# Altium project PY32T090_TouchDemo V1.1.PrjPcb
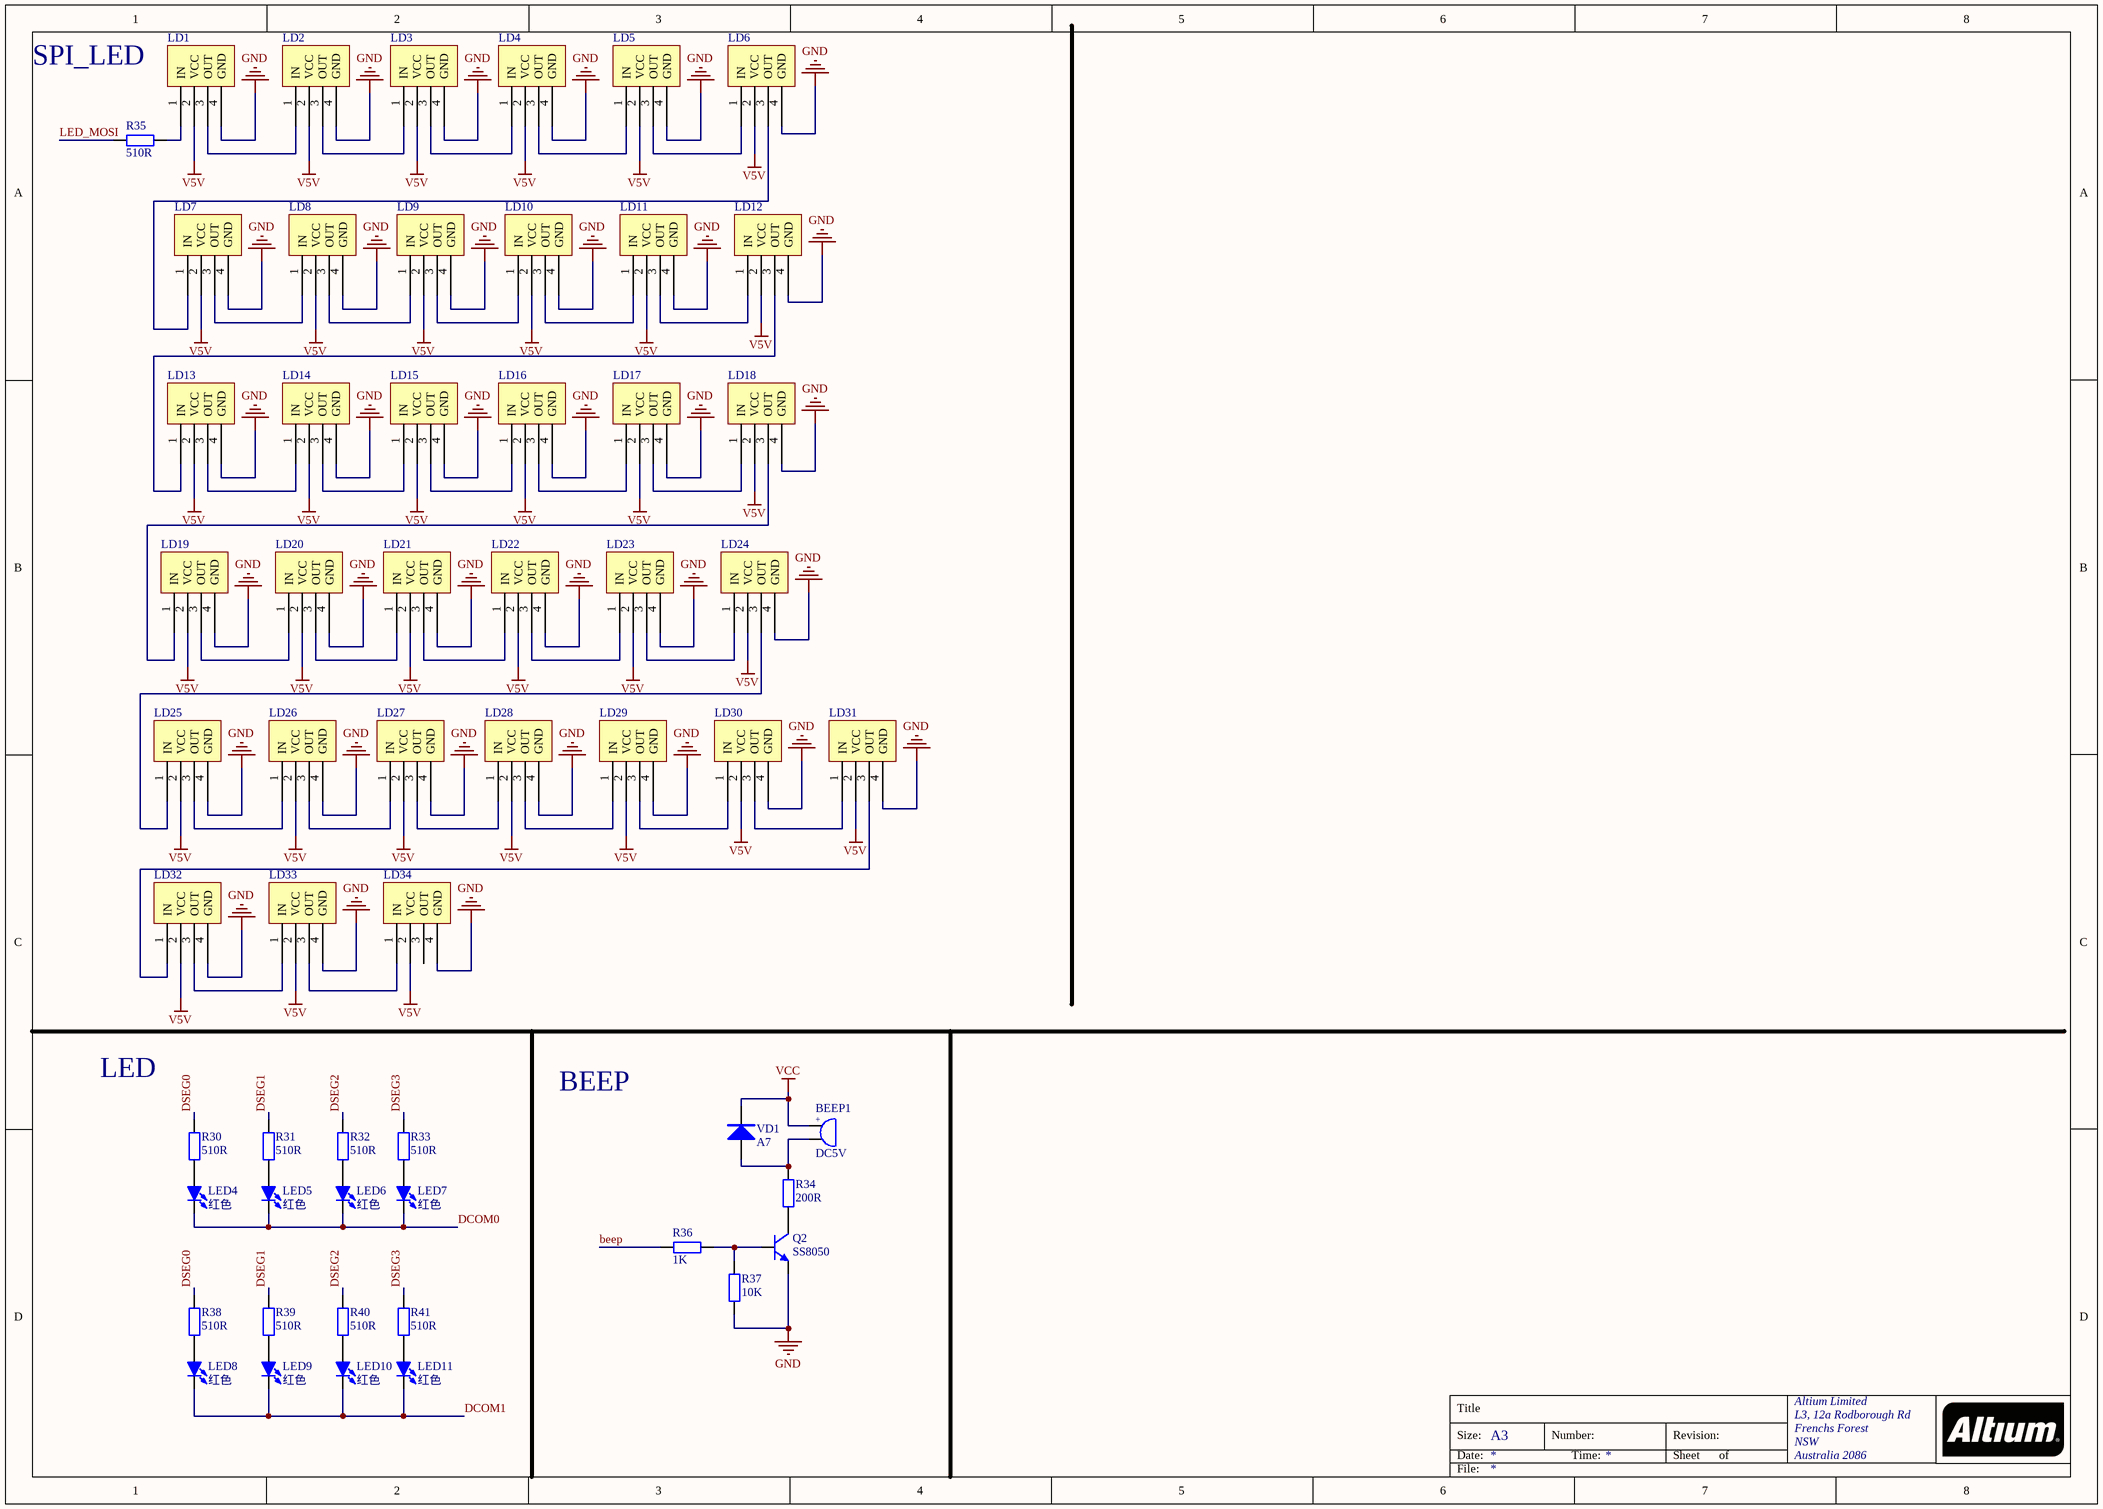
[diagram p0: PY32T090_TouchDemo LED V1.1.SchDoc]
2 sheets, 150 parts. Net scope: global (net labels, ports and power ports of the same name join across sheets).
Board file: PY32T090_TouchDemo V1.1.PcbDoc
Sheets:
  PY32T090_TouchDemo LED V1.1.SchDoc
  PY32T090_TouchDemo V1.1.SchDoc

## Sheet PY32T090_TouchDemo LED V1.1.SchDoc
size A3; Organization: Altium Limited; Address1: L3, 12a Rodborough Rd; Address2: Frenchs Forest; Address3: NSW; Address4: Australia 2086

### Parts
BEEP1  DC5V  [BEEP 5x9x5.5]
LD1  LED1  [LED_WS]  (value not drawn)
LD2  LED1  [LED_WS]  (value not drawn)
LD3  LED1  [LED_WS]  (value not drawn)
LD4  LED1  [LED_WS]  (value not drawn)
LD5  LED1  [LED_WS]  (value not drawn)
LD6  LED1  [LED_WS]  (value not drawn)
LD7  LED1  [LED_WS]  (value not drawn)
LD8  LED1  [LED_WS]  (value not drawn)
LD9  LED1  [LED_WS]  (value not drawn)
LD10  LED1  [LED_WS]  (value not drawn)
LD11  LED1  [LED_WS]  (value not drawn)
LD12  LED1  [LED_WS]  (value not drawn)
LD13  LED1  [LED_WS]  (value not drawn)
LD14  LED1  [LED_WS]  (value not drawn)
LD15  LED1  [LED_WS]  (value not drawn)
LD16  LED1  [LED_WS]  (value not drawn)
LD17  LED1  [LED_WS]  (value not drawn)
LD18  LED1  [LED_WS]  (value not drawn)
LD19  LED1  [LED_WS]  (value not drawn)
LD20  LED1  [LED_WS]  (value not drawn)
LD21  LED1  [LED_WS]  (value not drawn)
LD22  LED1  [LED_WS]  (value not drawn)
LD23  LED1  [LED_WS]  (value not drawn)
LD24  LED1  [LED_WS]  (value not drawn)
LD25  LED1  [LED_WS]  (value not drawn)
LD26  LED1  [LED_WS]  (value not drawn)
LD27  LED1  [LED_WS]  (value not drawn)
LD28  LED1  [LED_WS]  (value not drawn)
LD29  LED1  [LED_WS]  (value not drawn)
LD30  LED1  [LED_WS]  (value not drawn)
LD31  LED1  [LED_WS]  (value not drawn)
LD32  LED1  [LED_WS]  (value not drawn)
LD33  LED1  [LED_WS]  (value not drawn)
LD34  LED1  [LED_WS]  (value not drawn)
LED4  红色  [LED 0805G]
LED5  红色  [LED 0805G]
LED6  红色  [LED 0805G]
LED7  红色  [LED 0805G]
LED8  红色  [LED 0805G]
LED9  红色  [LED 0805G]
LED10  红色  [LED 0805G]
LED11  红色  [LED 0805G]
Q2  SS8050  [SOT23-3L]
R30  510R  [R 0603_L]
R31  510R  [R 0603_L]
R32  510R  [R 0603_L]
R33  510R  [R 0603_L]
R34  200R  [R 0603_L]
R35  510R  [R 0603_L]
R36  1K  [R 0603_L]
R37  10K  [R 0603_L]
R38  510R  [R 0603_L]
R39  510R  [R 0603_L]
R40  510R  [R 0603_L]
R41  510R  [R 0603_L]
VD1  A7  [SOD-123]

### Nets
GND: LD1.4(GND) LD2.4(GND) LD3.4(GND) LD4.4(GND) LD5.4(GND) LD6.4(GND) LD7.4(GND) LD8.4(GND) LD9.4(GND) LD10.4(GND) LD11.4(GND) LD12.4(GND) LD13.4(GND) LD14.4(GND) LD15.4(GND) LD16.4(GND) LD17.4(GND) LD18.4(GND) LD19.4(GND) LD20.4(GND) LD21.4(GND) LD22.4(GND) LD23.4(GND) LD24.4(GND) LD25.4(GND) LD26.4(GND) LD27.4(GND) LD28.4(GND) LD29.4(GND) LD30.4(GND) LD31.4(GND) LD32.4(GND) LD33.4(GND) LD34.4(GND) Q2.2(B) R37.1
V5V: LD1.2(VCC) LD2.2(VCC) LD3.2(VCC) LD4.2(VCC) LD5.2(VCC) LD6.2(VCC) LD7.2(VCC) LD8.2(VCC) LD9.2(VCC) LD10.2(VCC) LD11.2(VCC) LD12.2(VCC) LD13.2(VCC) LD14.2(VCC) LD15.2(VCC) LD16.2(VCC) LD17.2(VCC) LD18.2(VCC) LD19.2(VCC) LD20.2(VCC) LD21.2(VCC) LD22.2(VCC) LD23.2(VCC) LD24.2(VCC) LD25.2(VCC) LD26.2(VCC) LD27.2(VCC) LD28.2(VCC) LD29.2(VCC) LD30.2(VCC) LD31.2(VCC) LD32.2(VCC) LD33.2(VCC) LD34.2(VCC)
VCC: BEEP1.1 VD1.K
beep: R36.2
DCOM0: LED4.2(K) LED5.2(K) LED6.2(K) LED7.2(K)
DCOM1: LED8.2(K) LED9.2(K) LED10.2(K) LED11.2(K)
DSEG0: R30.1 R38.1
DSEG1: R31.1 R39.1
DSEG2: R32.1 R40.1
DSEG3: R33.1 R41.1
LED_MOSI: R35.1
NetBEEP1_2: BEEP1.2 R34.2 VD1.A
NetLD1_1: LD1.1(IN) R35.2
NetLD1_3: LD1.3(OUT) LD2.1(IN)
NetLD2_3: LD2.3(OUT) LD3.1(IN)
NetLD3_3: LD3.3(OUT) LD4.1(IN)
NetLD4_3: LD4.3(OUT) LD5.1(IN)
NetLD5_3: LD5.3(OUT) LD6.1(IN)
NetLD6_3: LD6.3(OUT) LD7.1(IN)
NetLD7_3: LD7.3(OUT) LD8.1(IN)
NetLD8_3: LD8.3(OUT) LD9.1(IN)
NetLD9_3: LD9.3(OUT) LD10.1(IN)
NetLD10_3: LD10.3(OUT) LD11.1(IN)
NetLD11_3: LD11.3(OUT) LD12.1(IN)
NetLD12_3: LD12.3(OUT) LD13.1(IN)
NetLD13_3: LD13.3(OUT) LD14.1(IN)
NetLD14_3: LD14.3(OUT) LD15.1(IN)
NetLD15_3: LD15.3(OUT) LD16.1(IN)
NetLD16_3: LD16.3(OUT) LD17.1(IN)
NetLD17_3: LD17.3(OUT) LD18.1(IN)
NetLD18_3: LD18.3(OUT) LD19.1(IN)
NetLD19_3: LD19.3(OUT) LD20.1(IN)
NetLD20_3: LD20.3(OUT) LD21.1(IN)
NetLD21_3: LD21.3(OUT) LD22.1(IN)
NetLD22_3: LD22.3(OUT) LD23.1(IN)
NetLD23_3: LD23.3(OUT) LD24.1(IN)
NetLD24_3: LD24.3(OUT) LD25.1(IN)
NetLD25_3: LD25.3(OUT) LD26.1(IN)
NetLD26_3: LD26.3(OUT) LD27.1(IN)
NetLD27_3: LD27.3(OUT) LD28.1(IN)
NetLD28_3: LD28.3(OUT) LD29.1(IN)
NetLD29_3: LD29.3(OUT) LD30.1(IN)
NetLD30_3: LD30.3(OUT) LD31.1(IN)
NetLD31_3: LD31.3(OUT) LD32.1(IN)
NetLD32_3: LD32.3(OUT) LD33.1(IN)
NetLD33_3: LD33.3(OUT) LD34.1(IN)
NetLED4_1: LED4.1(A) R30.2
NetLED5_1: LED5.1(A) R31.2
NetLED6_1: LED6.1(A) R32.2
NetLED7_1: LED7.1(A) R33.2
NetLED8_1: LED8.1(A) R38.2
NetLED9_1: LED9.1(A) R39.2
NetLED10_1: LED10.1(A) R40.2
NetLED11_1: LED11.1(A) R41.2
NetQ2_1: Q2.1(E) R36.1 R37.2
NetQ2_3: Q2.3(C) R34.1

Not connected (* = marked no-connect by the designer): LD34 3(OUT)

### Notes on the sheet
- SPI_LED
- LED
- BEEP

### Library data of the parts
BEEP1 = BEEP: 蜂鸣器; 版权归属: 源创客
LD1-LD34 = LED4020
LED4-LED11 = LED-SMD: 贴片LED; 版权归属: 源创客
Q2 = 8050-DIP: 高频放大-NPN型; 版权归属: 源创客; 属性: 40V 1.5A 1W 100MHZ
R30-R41 = R: 贴片电阻; 版权归属: 源创客
VD1 = DIODE

## Sheet PY32T090_TouchDemo V1.1.SchDoc
size A3; SheetNumber: 1; SheetTotal: 1
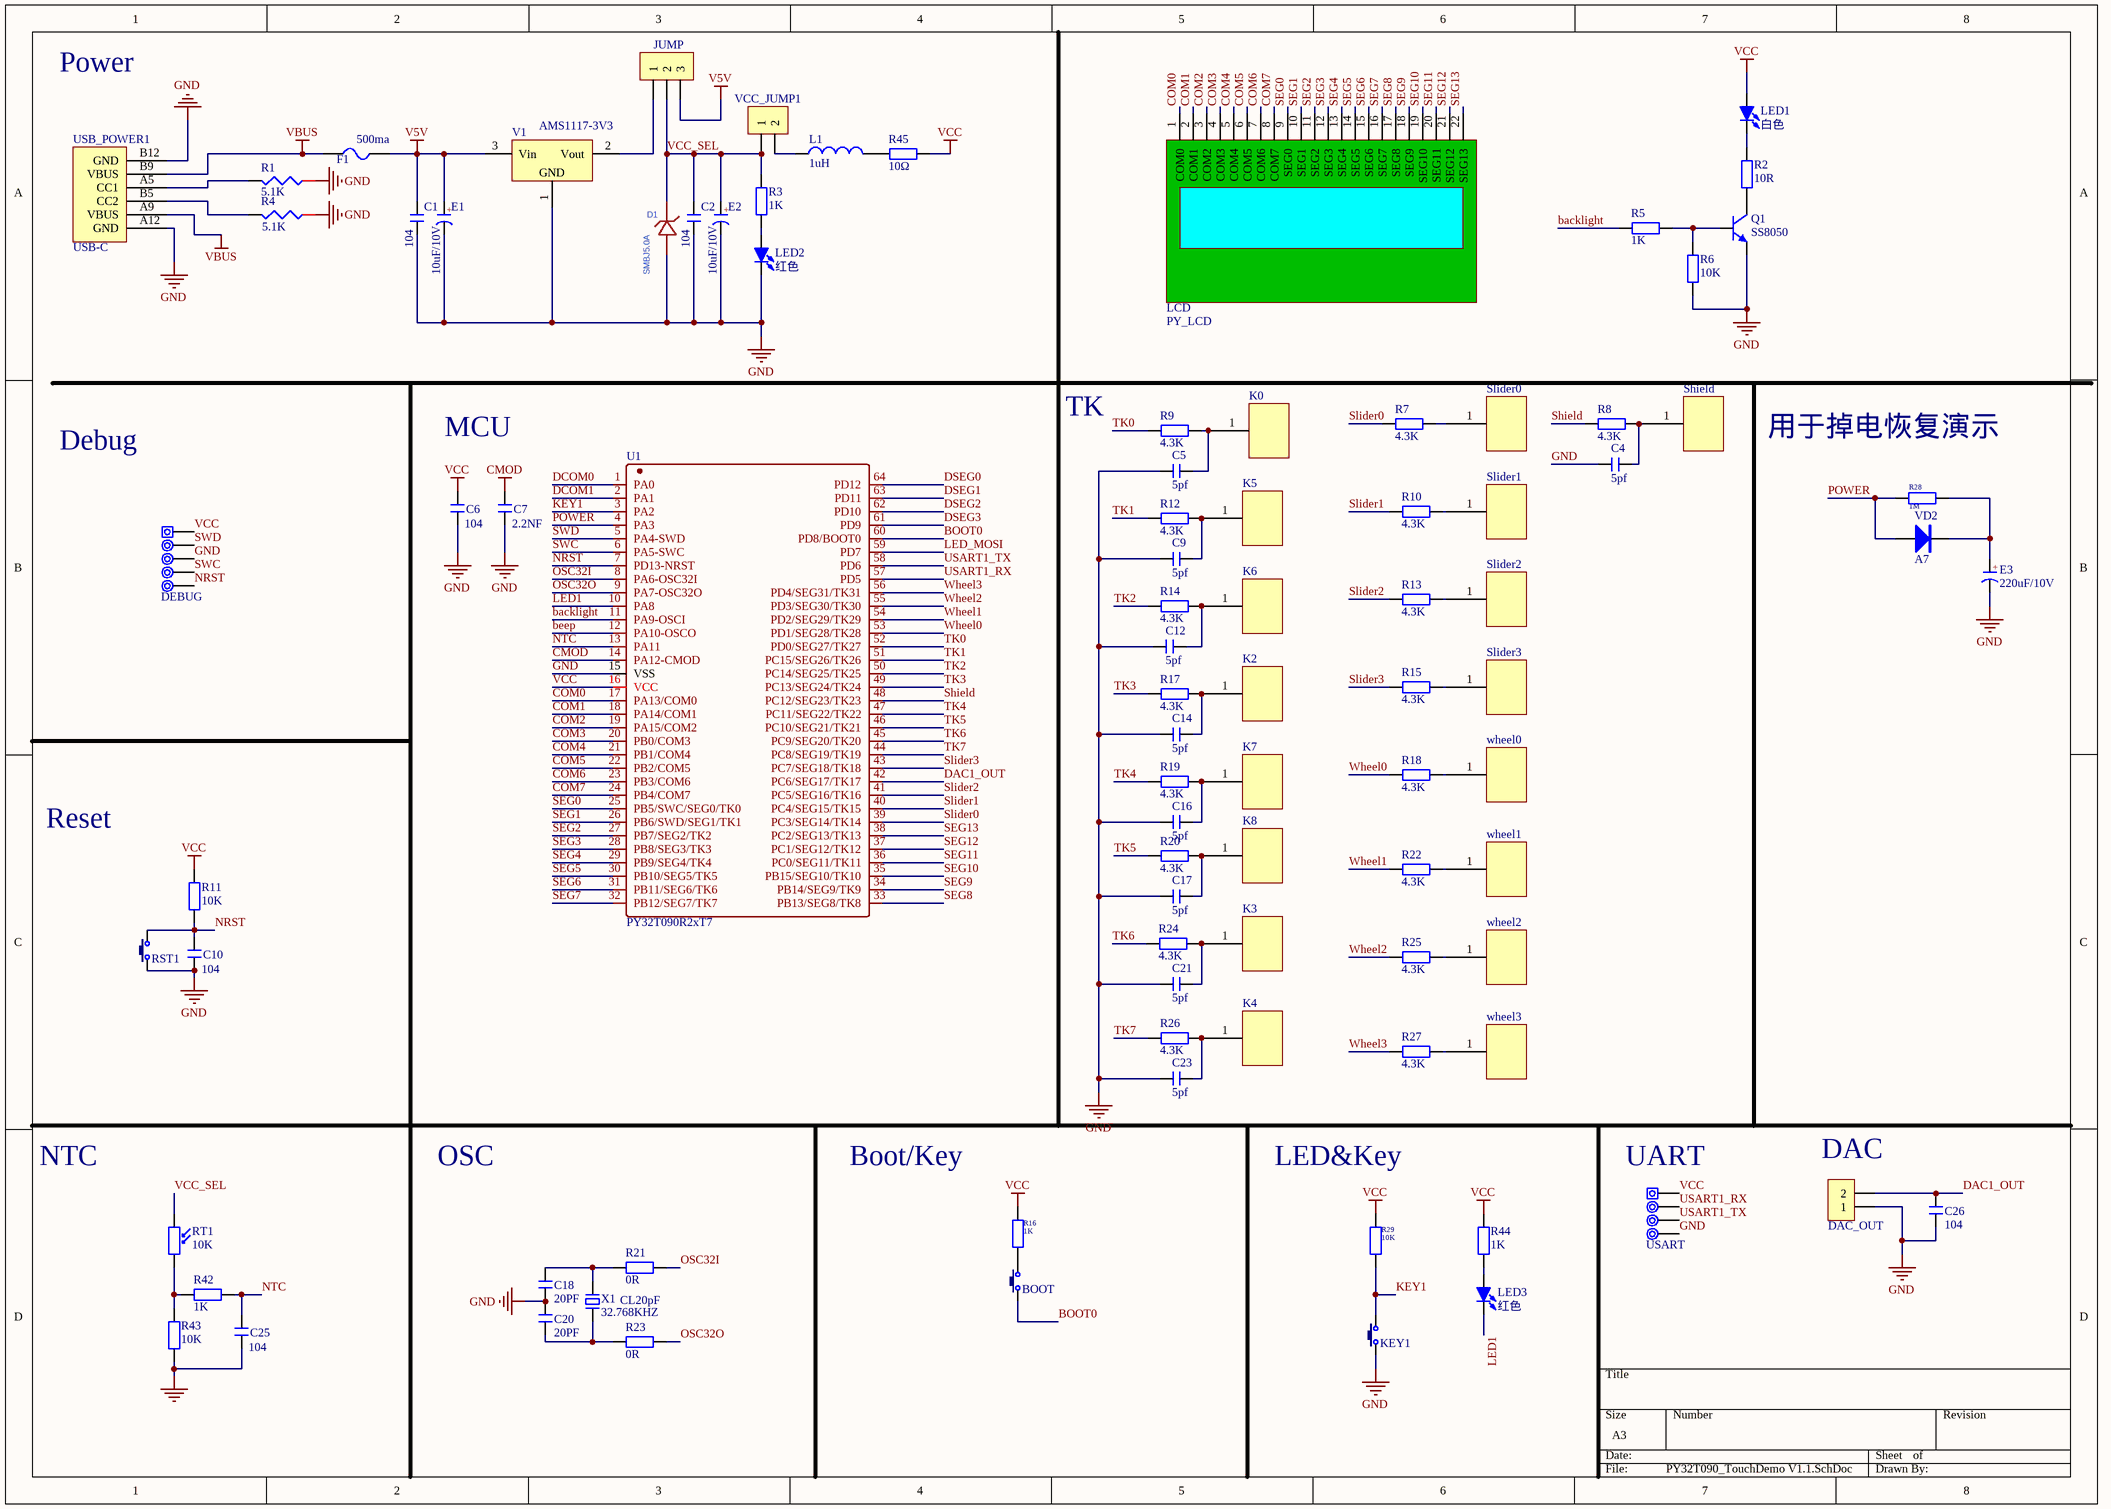
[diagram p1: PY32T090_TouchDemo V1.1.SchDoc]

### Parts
BOOT  6x6x5  [TSW SMD-3*6*5]  (value not drawn)
C1  104  [C 0603_L]
C2  104  [C 0603_L]
C4  5pf  [C 0603_L]
C5  5pf  [C 0603_L]
C6  104  [C 0603_L]
C7  2.2NF  [C 0603_L]
C9  5pf  [C 0603_L]
C10  104  [C 0603_L]
C12  5pf  [C 0603_L]
C14  5pf  [C 0603_L]
C16  5pf  [C 0603_L]
C17  5pf  [C 0603_L]
C18  20PF  [C 0603_L]
C20  20PF  [C 0603_L]
C21  5pf  [C 0603_L]
C23  5pf  [C 0603_L]
C25  104  [C 0603_L]
C26  104  [C 0603_L]
D1  SMBJ5.0A  [SMB_L4.6-W3.6-LS5.3-RD]
DAC_OUT  HDR-1X2  [HDR2.54-LI-2P]  (value not drawn)
DEBUG  ISP  [ISP_DIP_2.54_5P]  (value not drawn)
E1  10uF/10V  [C 0805_L]
E2  10uF/10V  [C 0805_L]
E3  220uF/10V  [CM A(3*5.4)]
F1  500ma  [FU 0805]
JUMP  HDR-1X3  [HDR2.54-LI-3P]  (value not drawn)
K0  Comment  [T-LED]  (value not drawn)
K2  Comment  [T-LED]  (value not drawn)
K3  Comment  [T-LED]  (value not drawn)
K4  Comment  [T-LED]  (value not drawn)
K5  Comment  [T-LED]  (value not drawn)
K6  Comment  [T-LED]  (value not drawn)
K7  Comment  [T-LED]  (value not drawn)
K8  Comment  [T-LED]  (value not drawn)
KEY1  6x6x5  [TSW SMD-3*6*5]  (value not drawn)
L1  1uH  [L 0805_L]
LCD  PY_LCD  [HDR2.54-WI-2x11P]
LED1  白色  [LED 0805G]
LED2  红色  [LED 0805W]
LED3  红色  [LED 0805W]
Q1  SS8050  [SOT23-3L]
R1  5.1K  [R 0603_L]
R2  10R  [R 0805_L]
R3  1K  [R 0603_L]
R4  5.1K  [R 0603_L]
R5  1K  [R 0603_L]
R6  10K  [R 0603_L]
R7  4.3K  [R 0603_L]
R8  4.3K  [R 0603_L]
R9  4.3K  [R 0603_L]
R10  4.3K  [R 0603_L]
R11  10K  [R 0603_L]
R12  4.3K  [R 0603_L]
R13  4.3K  [R 0603_L]
R14  4.3K  [R 0603_L]
R15  4.3K  [R 0603_L]
R16  1K  [R 0603_L]
R17  4.3K  [R 0603_L]
R18  4.3K  [R 0603_L]
R19  4.3K  [R 0603_L]
R20  4.3K  [R 0603_L]
R21  0R  [R 0603_L]
R22  4.3K  [R 0603_L]
R23  0R  [R 0603_L]
R24  4.3K  [R 0603_L]
R25  4.3K  [R 0603_L]
R26  4.3K  [R 0603_L]
R27  4.3K  [R 0603_L]
R28  1M  [R 0603_L]
R29  10K  [R 0603_L]
R42  1K  [R 0603_L]
R43  10K  [R 0603_L]
R44  1K  [R 0603_L]
R45  10Ω  [R 0805_L]
RST1  6x6x5  [TSW SMD-3*6*5]  (value not drawn)
RT1  10K  [RG5528]
Shield  Comment  [T-LED]  (value not drawn)
Slider0  Comment  [T-LED]  (value not drawn)
Slider1  Comment  [T-LED]  (value not drawn)
Slider2  Comment  [T-LED]  (value not drawn)
Slider3  Comment  [T-LED]  (value not drawn)
U1  PY32T090R2xT7  [LQFP64 10x10_L]
USART  ISP  [ISP_DIP_2.54_4P]  (value not drawn)
USB_POWER1  USB-C  [USB-C/S_C]
V1  AMS1117-3V3  [SOT223_N]
VCC_JUMP1  HDR-1X2  [HDR2.54-LI-2P]  (value not drawn)
VD2  A7  [SOD-123]
wheel0  Comment  [T-LED]  (value not drawn)
wheel1  Comment  [T-LED]  (value not drawn)
wheel2  Comment  [T-LED]  (value not drawn)
wheel3  Comment  [T-LED]  (value not drawn)
X1  32.768KHZ  负载电容: CL20pF  [OSC-3x8-WI-A]

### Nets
CMOD: C7.2 U1.14(PA12-CMOD)
GND: C1.1 C2.1 C4.1 C5.1 C6.1 C7.1 C9.1 C10.1 C12.1 C14.1 C16.1 C17.1 C18.1 C20.2 C21.1 C23.1 C25.1 C26.1 D1.2 DAC_OUT.1 DEBUG.3 E1.2(K) E2.2(K) E3.2(K) KEY1.1 LED2.2(K) Q1.2(B) R1.1 R4.1 R6.1 R43.2 RST1.1 U1.15(VSS) USART.4 USB_POWER1.A12(GND) USB_POWER1.B12(GND) V1.1(GND)
V5V: C1.2 E1.1(A) F1.2 JUMP.3 V1.3(Vin)
VBUS: F1.1 USB_POWER1.A9(VBUS) USB_POWER1.B9(VBUS)
VCC: C6.2 DEBUG.1 LED1.1(A) R11.2 R16.2 R29.2 R44.2 R45.2 U1.16(VCC) USART.1
backlight: R5.2 U1.11(PA9-OSCI)
beep: U1.12(PA10-OSCO)
BOOT0: BOOT.1 U1.60(PD8/BOOT0)
COM0: LCD.1(COM0) U1.17(PA13/COM0)
COM1: LCD.2(COM1) U1.18(PA14/COM1)
COM2: LCD.3(COM2) U1.19(PA15/COM2)
COM3: LCD.4(COM3) U1.20(PB0/COM3)
COM4: LCD.5(COM4) U1.21(PB1/COM4)
COM5: LCD.6(COM5) U1.22(PB2/COM5)
COM6: LCD.7(COM6) U1.23(PB3/COM6)
COM7: LCD.8(COM7) U1.24(PB4/COM7)
DAC1_OUT: C26.2 DAC_OUT.2 U1.42(PC6/SEG17/TK17)
DCOM0: U1.1(PA0)
DCOM1: U1.2(PA1)
DSEG0: U1.64(PD12)
DSEG1: U1.63(PD11)
DSEG2: U1.62(PD10)
DSEG3: U1.61(PD9)
KEY1: KEY1.2 R29.1 U1.3(PA2)
LED1: LED3.2(K) U1.10(PA8)
LED_MOSI: U1.59(PD7)
NRST: C10.2 DEBUG.5 R11.1 RST1.2 U1.7(PD13-NRST)
NTC: C25.2 R42.2 U1.13(PA11)
OSC32I: R21.1 U1.8(PA6-OSC32I)
OSC32O: R23.1 U1.9(PA7-OSC32O)
POWER: R28.1 U1.4(PA3) VD2.A
SEG0: LCD.9(SEG0) U1.25(PB5/SWC/SEG0/TK0)
SEG1: LCD.10(SEG1) U1.26(PB6/SWD/SEG1/TK1)
SEG2: LCD.11(SEG2) U1.27(PB7/SEG2/TK2)
SEG3: LCD.12(SEG3) U1.28(PB8/SEG3/TK3)
SEG4: LCD.13(SEG4) U1.29(PB9/SEG4/TK4)
SEG5: LCD.14(SEG5) U1.30(PB10/SEG5/TK5)
SEG6: LCD.15(SEG6) U1.31(PB11/SEG6/TK6)
SEG7: LCD.16(SEG7) U1.32(PB12/SEG7/TK7)
SEG8: LCD.17(SEG8) U1.33(PB13/SEG8/TK8)
SEG9: LCD.18(SEG9) U1.34(PB14/SEG9/TK9)
SEG10: LCD.19(SEG10) U1.35(PB15/SEG10/TK10)
SEG11: LCD.20(SEG11) U1.36(PC0/SEG11/TK11)
SEG12: LCD.21(SEG12) U1.37(PC1/SEG12/TK12)
SEG13: LCD.22(SEG13) U1.38(PC2/SEG13/TK13)
Shield: R8.1 U1.48(PC12/SEG23/TK23)
Slider0: R7.1 U1.39(PC3/SEG14/TK14)
Slider1: R10.1 U1.40(PC4/SEG15/TK15)
Slider2: R13.1 U1.41(PC5/SEG16/TK16)
Slider3: R15.1 U1.43(PC7/SEG18/TK18)
SWC: DEBUG.4 U1.6(PA5-SWC)
SWD: DEBUG.2 U1.5(PA4-SWD)
TK0: R9.1 U1.52(PD0/SEG27/TK27)
TK1: R12.1 U1.51(PC15/SEG26/TK26)
TK2: R14.1 U1.50(PC14/SEG25/TK25)
TK3: R17.1 U1.49(PC13/SEG24/TK24)
TK4: R19.1 U1.47(PC11/SEG22/TK22)
TK5: R20.1 U1.46(PC10/SEG21/TK21)
TK6: R24.1 U1.45(PC9/SEG20/TK20)
TK7: R26.1 U1.44(PC8/SEG19/TK19)
USART1_RX: U1.57(PD5) USART.2
USART1_TX: U1.58(PD6) USART.3
VCC_SEL: C2.2 D1.1 E2.1(A) JUMP.2 R3.2 RT1.1 VCC_JUMP1.1
Wheel0: R18.1 U1.53(PD1/SEG28/TK28)
Wheel1: R22.1 U1.54(PD2/SEG29/TK29)
Wheel2: R25.1 U1.55(PD3/SEG30/TK30)
Wheel3: R27.1 U1.56(PD4/SEG31/TK31)
NetBOOT_2: BOOT.2 R16.1
NetC4_2: C4.2 R8.2 Shield.1
NetC5_2: C5.2 K0.1 R9.2
NetC9_2: C9.2 K5.1 R12.2
NetC12_2: C12.2 K6.1 R14.2
NetC14_2: C14.2 K2.1 R17.2
NetC16_2: C16.2 K7.1 R19.2
NetC17_2: C17.2 K8.1 R20.2
NetC18_2: C18.2 R21.2 X1.1
NetC20_1: C20.1 R23.2 X1.2
NetC21_2: C21.2 K3.1 R24.2
NetC23_2: C23.2 K4.1 R26.2
NetE3_1: E3.1(A) R28.2 VD2.K
NetJUMP_1: JUMP.1 V1.2(Vout)
NetL1_1: L1.1 VCC_JUMP1.2
NetL1_2: L1.2 R45.1
NetLED1_2: LED1.2(K) R2.2
NetLED2_1: LED2.1(A) R3.1
NetLED3_1: LED3.1(A) R44.1
NetQ1_1: Q1.1(E) R5.1 R6.2
NetQ1_3: Q1.3(C) R2.1
NetR1_2: R1.2 USB_POWER1.A5(CC1)
NetR4_2: R4.2 USB_POWER1.B5(CC2)
NetR7_2: R7.2 Slider0.1
NetR10_2: R10.2 Slider1.1
NetR13_2: R13.2 Slider2.1
NetR15_2: R15.2 Slider3.1
NetR18_2: R18.2 wheel0.1
NetR22_2: R22.2 wheel1.1
NetR25_2: R25.2 wheel2.1
NetR27_2: R27.2 wheel3.1
NetR42_1: R42.1 R43.1 RT1.2

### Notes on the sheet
- Power
- Debug
- MCU
- TK
- 用于掉电恢复演示
- Reset
- NTC
- OSC
- Boot/Key
- LED&Key
- (near USART) UART
- (near DAC_OUT) DAC

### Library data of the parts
BOOT KEY1 RST1 = TSW DIP-2Pin-6x6: 2脚直插6x6轻触开关; BOM名称: 2脚轻触开关; 版权归属: 源创客
C1 C2 C4-C7 C9 C10 C12 C14 C16-C18 C20 C21 C23 C25 C26 = C: 无极性贴片电容; 版权归属: 源创客; 材质: X7R
D1 = SMBJ5.0A_C83333: Manufacturer: Littelfuse(美国力特); Add into BOM: yes; Reverse Stand-Off Voltage (Vrwm): 5V; Maximum Clamping Voltage: 9.2V; Peak Pulse Current (Ipp)@10/1000us: 65.3A; Peak Pulse Power Dissipation (Ppp)@10/1000us: 600W; Breakdown Voltage: 6.4V; Type: TVS
DAC_OUT VCC_JUMP1 = Header 2: 2P接插件; 版权归属: 源创客
DEBUG = ISP_5Pin: 程序下载端口; 版权归属: 源创客
E1-E3 = C-CM: 贴片电解电容; 版权归属: 源创客
F1 = FU: 贴片保险丝; 版权归属: 源创客
JUMP = Header 3: 3P接插件; 版权归属: 源创客
K0 K2-K8 Shield Slider0-Slider3 wheel0-wheel3 = TK
L1 = L: 小功率贴片电感; 版权归属: 源创客
LED1-LED3 = LED-SMD: 贴片LED; 版权归属: 源创客
Q1 = 8050-DIP: as Q2 on sheet PY32T090_TouchDemo LED V1.1
R1 R4 = R
R2 R3 R5-R15 R17-R27 R42-R45 = R: 贴片电阻; 版权归属: 源创客
R16 R28 = Res: Resistor; 器件封装(外观): 0603; Value: 10K
R29 = Res: Resistor; 器件封装(外观): 0603
RT1 = RG5528: 光敏电阻; 版权归属: 源创客
U1 = PY32T092
USART = ISP_4Pin: 程序下载端口; 版权归属: 源创客
USB_POWER1 = USB-C_6P/S: USB-C_6P型母接口; BOM名称: USB-C型母接口; 版权归属: 源创客
V1 = AMS1117: 三端稳压芯片; BOM名称: 稳压芯片; 版权归属: 源创客
VD2 = DIODE
X1 = XTAL-2P: 2脚无源脚晶振; 版权归属: 源创客

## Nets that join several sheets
GND: PY32T090_TouchDemo LED V1.1 (36 pins), PY32T090_TouchDemo V1.1 (37 pins)
V5V: PY32T090_TouchDemo LED V1.1 (34 pins), PY32T090_TouchDemo V1.1 (5 pins)
VCC: PY32T090_TouchDemo LED V1.1 (BEEP1.1 VD1.K), PY32T090_TouchDemo V1.1 (10 pins)
beep: PY32T090_TouchDemo LED V1.1 (R36.2), PY32T090_TouchDemo V1.1 (U1.12)
DCOM0: PY32T090_TouchDemo LED V1.1 (LED4.2 LED5.2 LED6.2 LED7.2), PY32T090_TouchDemo V1.1 (U1.1)
DCOM1: PY32T090_TouchDemo LED V1.1 (LED8.2 LED9.2 LED10.2 LED11.2), PY32T090_TouchDemo V1.1 (U1.2)
DSEG0: PY32T090_TouchDemo LED V1.1 (R30.1 R38.1), PY32T090_TouchDemo V1.1 (U1.64)
DSEG1: PY32T090_TouchDemo LED V1.1 (R31.1 R39.1), PY32T090_TouchDemo V1.1 (U1.63)
DSEG2: PY32T090_TouchDemo LED V1.1 (R32.1 R40.1), PY32T090_TouchDemo V1.1 (U1.62)
DSEG3: PY32T090_TouchDemo LED V1.1 (R33.1 R41.1), PY32T090_TouchDemo V1.1 (U1.61)
LED_MOSI: PY32T090_TouchDemo LED V1.1 (R35.1), PY32T090_TouchDemo V1.1 (U1.59)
